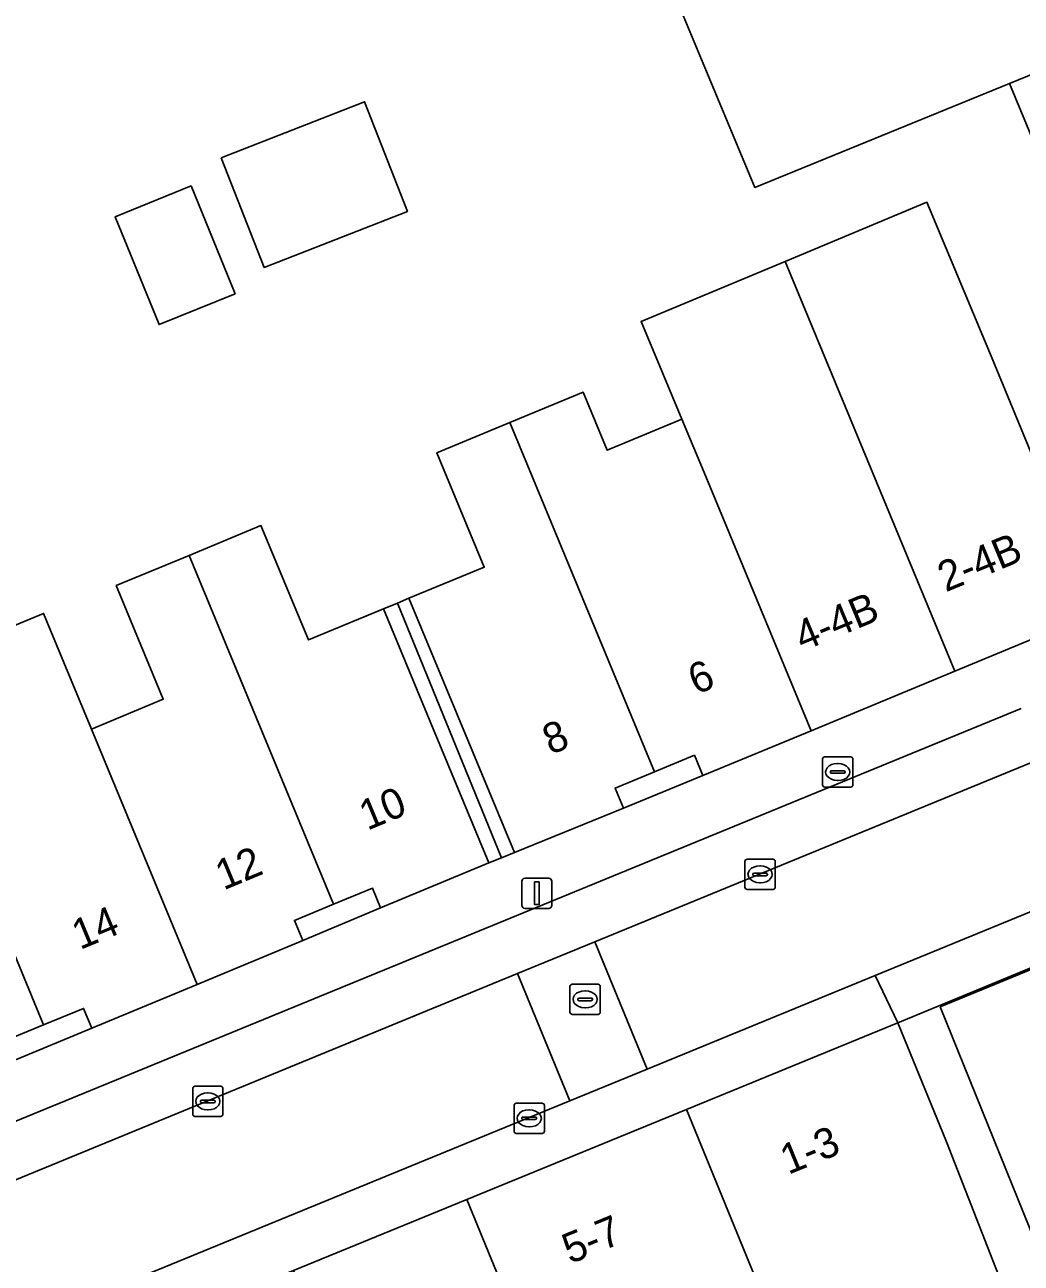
# Model space of a CAD drawing. Extents: x 159371 to 159986, y 382987 to 383597.
# Drawn here: x 159877.92 to 159910.85, y 383362.53 to 383403.47 of the extents above; entities that cross this region are included whole.
import ezdxf

# ---------------------------------------------------------------- set-up
doc = ezdxf.new("R2010")
doc.units = 0
for name, color, linetype in [('IMGEO_Brandkraan', 7, 'Continuous'), ('IMGEO_Erf', 7, 'Continuous'), ('IMGEO_Kolk', 7, 'Continuous'), ('IMGEO_Lichtmast', 7, 'Continuous'), ('IMGEO_Pand', 7, 'Continuous'), ('IMGEO_Pand_nummerreeks', 7, 'Continuous'), ('IMGEO_Pand_overbouw', 7, 'Continuous'), ('IMGEO_Pand_vergunning_verleend', 7, 'Continuous'), ('IMGEO_Parkeervlak_open', 7, 'Continuous'), ('IMGEO_Rijbaan_lokaal_open', 7, 'Continuous'), ('IMGEO_Rioolput', 7, 'Continuous'), ('IMGEO_Voetpad_open', 7, 'Continuous')]:
    doc.layers.add(name, color=color, linetype=linetype)

msp = doc.modelspace()

# ---------------------------------------------------------------- linework, layer by layer
at = {"layer": 'IMGEO_Brandkraan'}
for p, q in [((159904.359, 383379.27), (159905.211, 383379.27)), ((159904.284, 383378.344), (159904.284, 383379.196)), ((159904.772, 383379.05), (159904.797, 383379.05)), ((159905.285, 383379.196), (159905.285, 383378.344)), ((159904.543, 383378.764), (159904.543, 383378.776)), ((159904.981, 383378.727), (159904.583, 383378.727)), ((159904.586, 383378.813), (159904.984, 383378.813)), ((159904.795, 383378.49), (159904.77, 383378.49)), ((159905.027, 383378.776), (159905.027, 383378.764)), ((159905.211, 383378.27), (159904.359, 383378.27))]:
    msp.add_line(p, q, dxfattribs=at)
for points in [[(159904.359, 383379.27), (159905.211, 383379.27)], [(159904.284, 383378.344), (159904.284, 383379.196)], [(159905.285, 383379.196), (159905.285, 383378.344)], [(159905.211, 383378.27), (159904.359, 383378.27)]]:
    msp.add_lwpolyline(points, dxfattribs=at)
for centre, radius, start, end in [((159904.361, 383379.194), 0.0765, 91.552, 178.448), ((159904.361, 383379.194), 0.0765, 91.552, 178.448), ((159905.209, 383379.194), 0.0765, 1.552, 88.448), ((159905.209, 383379.194), 0.0765, 1.552, 88.448), ((159904.583, 383378.773), 0.0403, 85.8775, 175.7526), ((159904.58, 383378.763), 0.0366, 178.938, 274.7102), ((159904.984, 383378.77), 0.043, 264.8664, 352.4533), ((159904.988, 383378.775), 0.0386, 1.7309, 96.639), ((159904.361, 383378.346), 0.0765, 181.552, 268.448), ((159904.361, 383378.346), 0.0765, 181.552, 268.448), ((159905.209, 383378.346), 0.0765, 271.552, 358.448), ((159905.209, 383378.346), 0.0765, 271.552, 358.448)]:
    msp.add_arc(centre, radius, start, end, dxfattribs=at)
for centre, major_axis, ratio, start_param, end_param in [((159904.771, 383378.77), (-0.387, 0.002), 0.722429, 4.712389, 7.853982), ((159904.796, 383378.77), (-0.39, 0.002), 0.717154, 1.570796, 4.712389)]:
    msp.add_ellipse(centre, major_axis=major_axis, ratio=ratio, start_param=start_param, end_param=end_param, dxfattribs=at)
at = {"layer": 'IMGEO_Erf'}
for points in [[(159914.018, 383392.946), (159910.463, 383401.527), (159902.048, 383398.093), (159898.736, 383406.04)], [(159876.16, 383383.024), (159878.542, 383384.012), (159880.125, 383380.191), (159882.499, 383381.175), (159880.942, 383384.933), (159883.351, 383385.931), (159885.727, 383386.916), (159887.294, 383383.134), (159889.776, 383384.162), (159891.341, 383380.385), (159893.256, 383375.765), (159893.678, 383375.937), (159894.099, 383376.108), (159892.185, 383380.728), (159890.617, 383384.511), (159893.102, 383385.541), (159891.536, 383389.318), (159893.955, 383390.32), (159896.375, 383391.323), (159897.169, 383389.407), (159899.635, 383390.428), (159898.286, 383393.665), (159903.049, 383395.65), (159907.734, 383397.602), (159909.884, 383392.444), (159911.446, 383388.674)], [(159938.072, 383368.867), (159934.754, 383367.475), (159932.558, 383372.707), (159933.96, 383373.295), (159932.124, 383377.671), (159934.042, 383378.476), (159932.918, 383381.155), (159927.224, 383378.895), (159915.917, 383374.262), (159914.973, 383373.871), (159906.767, 383370.475), (159908.377, 383366.545), (159911.987, 383357.288)]]:
    msp.add_lwpolyline(points, dxfattribs=at)
for points in [[(159884.413, 383399.072), (159889.145, 383400.924), (159890.563, 383397.303), (159885.831, 383395.451)], [(159883.421, 383398.145), (159884.87, 383394.577), (159882.362, 383393.558), (159880.913, 383397.126)]]:
    msp.add_lwpolyline(points, close=True, dxfattribs=at)
at = {"layer": 'IMGEO_Kolk'}
for p, q in [((159901.719, 383374.96), (159901.719, 383375.812)), ((159901.794, 383375.886), (159902.646, 383375.886)), ((159902.207, 383375.666), (159902.232, 383375.666)), ((159902.72, 383375.812), (159902.72, 383374.96)), ((159901.978, 383375.38), (159901.978, 383375.392)), ((159902.416, 383375.343), (159902.018, 383375.343)), ((159902.021, 383375.429), (159902.419, 383375.429)), ((159902.462, 383375.392), (159902.462, 383375.38)), ((159902.646, 383374.886), (159901.794, 383374.886)), ((159902.23, 383375.106), (159902.205, 383375.106)), ((159883.47, 383367.456), (159883.47, 383368.308)), ((159883.545, 383368.382), (159884.397, 383368.382)), ((159884.471, 383368.308), (159884.471, 383367.456)), ((159883.729, 383367.876), (159883.729, 383367.888)), ((159884.167, 383367.839), (159883.769, 383367.839)), ((159883.772, 383367.925), (159884.17, 383367.925)), ((159883.958, 383368.162), (159883.983, 383368.162)), ((159884.213, 383367.888), (159884.213, 383367.876)), ((159894.164, 383367.822), (159895.016, 383367.822)), ((159884.397, 383367.382), (159883.545, 383367.382)), ((159883.981, 383367.602), (159883.956, 383367.602)), ((159894.089, 383366.896), (159894.089, 383367.748)), ((159894.391, 383367.365), (159894.789, 383367.365)), ((159894.577, 383367.602), (159894.602, 383367.602)), ((159895.09, 383367.748), (159895.09, 383366.896)), ((159894.348, 383367.316), (159894.348, 383367.328)), ((159894.786, 383367.279), (159894.388, 383367.279)), ((159894.6, 383367.042), (159894.575, 383367.042)), ((159894.832, 383367.328), (159894.832, 383367.316)), ((159895.016, 383366.822), (159894.164, 383366.822))]:
    msp.add_line(p, q, dxfattribs=at)
for points in [[(159901.719, 383374.96), (159901.719, 383375.812)], [(159901.794, 383375.886), (159902.646, 383375.886)], [(159902.72, 383375.812), (159902.72, 383374.96)], [(159902.646, 383374.886), (159901.794, 383374.886)], [(159883.47, 383367.456), (159883.47, 383368.308)], [(159883.545, 383368.382), (159884.397, 383368.382)], [(159884.471, 383368.308), (159884.471, 383367.456)], [(159894.164, 383367.822), (159895.016, 383367.822)], [(159884.397, 383367.382), (159883.545, 383367.382)], [(159894.089, 383366.896), (159894.089, 383367.748)], [(159895.09, 383367.748), (159895.09, 383366.896)], [(159895.016, 383366.822), (159894.164, 383366.822)]]:
    msp.add_lwpolyline(points, dxfattribs=at)
for centre, radius, start, end in [((159901.796, 383375.81), 0.0765, 91.552, 178.448), ((159901.796, 383375.81), 0.0765, 91.552, 178.448), ((159902.644, 383375.81), 0.0765, 1.552, 88.448), ((159902.644, 383375.81), 0.0765, 1.552, 88.448), ((159902.018, 383375.389), 0.0403, 85.8775, 175.7526), ((159902.015, 383375.379), 0.0366, 178.938, 274.7102), ((159902.419, 383375.386), 0.043, 264.8664, 352.4533), ((159902.423, 383375.391), 0.0386, 1.7309, 96.639), ((159901.796, 383374.962), 0.0765, 181.552, 268.448), ((159901.796, 383374.962), 0.0765, 181.552, 268.448), ((159902.644, 383374.962), 0.0765, 271.552, 358.448), ((159902.644, 383374.962), 0.0765, 271.552, 358.448), ((159883.547, 383368.306), 0.0765, 91.552, 178.448), ((159883.547, 383368.306), 0.0765, 91.552, 178.448), ((159884.395, 383368.306), 0.0765, 1.552, 88.448), ((159884.395, 383368.306), 0.0765, 1.552, 88.448), ((159883.769, 383367.885), 0.0403, 85.8775, 175.7526), ((159883.766, 383367.875), 0.0366, 178.938, 274.7102), ((159884.17, 383367.882), 0.043, 264.8664, 352.4533), ((159884.174, 383367.887), 0.0386, 1.7309, 96.639), ((159894.166, 383367.746), 0.0765, 91.552, 178.448), ((159894.166, 383367.746), 0.0765, 91.552, 178.448), ((159895.014, 383367.746), 0.0765, 1.552, 88.448), ((159895.014, 383367.746), 0.0765, 1.552, 88.448), ((159883.547, 383367.458), 0.0765, 181.552, 268.448), ((159883.547, 383367.458), 0.0765, 181.552, 268.448), ((159884.395, 383367.458), 0.0765, 271.552, 358.448), ((159884.395, 383367.458), 0.0765, 271.552, 358.448), ((159894.388, 383367.325), 0.0403, 85.8775, 175.7526), ((159894.793, 383367.327), 0.0386, 1.7309, 96.639), ((159894.385, 383367.315), 0.0366, 178.938, 274.7102), ((159894.789, 383367.322), 0.043, 264.8664, 352.4533), ((159894.166, 383366.898), 0.0765, 181.552, 268.448), ((159894.166, 383366.898), 0.0765, 181.552, 268.448), ((159895.014, 383366.898), 0.0765, 271.552, 358.448), ((159895.014, 383366.898), 0.0765, 271.552, 358.448)]:
    msp.add_arc(centre, radius, start, end, dxfattribs=at)
for centre, major_axis, ratio, start_param, end_param in [((159902.206, 383375.386), (-0.387, 0.002), 0.722429, 4.712389, 7.853982), ((159902.231, 383375.386), (-0.39, 0.002), 0.717154, 1.570796, 4.712389), ((159883.957, 383367.882), (-0.387, 0.002), 0.722429, 4.712389, 7.853982), ((159883.982, 383367.882), (-0.39, 0.002), 0.717154, 1.570796, 4.712389), ((159894.576, 383367.322), (-0.387, 0.002), 0.722429, 4.712389, 7.853982), ((159894.601, 383367.322), (-0.39, 0.002), 0.717154, 1.570796, 4.712389)]:
    msp.add_ellipse(centre, major_axis=major_axis, ratio=ratio, start_param=start_param, end_param=end_param, dxfattribs=at)
at = {"layer": 'IMGEO_Lichtmast'}
for p, q in [((159894.345, 383374.36), (159894.345, 383375.16)), ((159894.345, 383375.16), (159894.345, 383374.36)), ((159894.445, 383375.26), (159895.235, 383375.26)), ((159895.235, 383375.26), (159894.445, 383375.26)), ((159895.335, 383375.16), (159895.335, 383374.36)), ((159895.335, 383374.36), (159895.335, 383375.16)), ((159895.235, 383374.26), (159894.445, 383374.26)), ((159894.445, 383374.26), (159895.235, 383374.26))]:
    msp.add_line(p, q, dxfattribs=at)
msp.add_lwpolyline([(159894.765, 383375.135), (159894.915, 383375.135), (159894.915, 383374.385), (159894.765, 383374.385), (159894.765, 383375.135)], dxfattribs=at)
for centre, start, end in [((159894.445, 383375.16), 90, 180), ((159894.445, 383375.16), 90, 180), ((159895.235, 383375.16), 0, 90), ((159895.235, 383375.16), 360, 90), ((159894.445, 383374.36), 180, 270), ((159894.445, 383374.36), 180, 270), ((159895.235, 383374.36), 270, 0), ((159895.235, 383374.36), 270, 0)]:
    msp.add_arc(centre, 0.1, start, end, dxfattribs=at)
at = {"layer": 'IMGEO_Pand'}
for points in [[(159929.666, 383409.619), (159926.604, 383416.76), (159923.474, 383415.417), (159923.137, 383416.203), (159914.242, 383412.388), (159898.736, 383406.04), (159902.048, 383398.093), (159910.463, 383401.527), (159916.891, 383404.15)], [(159929.666, 383409.619), (159916.891, 383404.15), (159910.463, 383401.527), (159914.018, 383392.946), (159916.615, 383394.023), (159917.049, 383394.203), (159916.207, 383396.235), (159915.325, 383398.371), (159915.519, 383398.455), (159915.982, 383398.653), (159924.094, 383402.131), (159925.483, 383398.882), (159928.324, 383400.063), (159932.941, 383401.982)], [(159884.413, 383399.072), (159885.831, 383395.451), (159890.563, 383397.303), (159889.145, 383400.924)], [(159883.421, 383398.145), (159880.913, 383397.126), (159882.362, 383393.558), (159884.87, 383394.577)], [(159903.049, 383395.65), (159908.654, 383382.104), (159913.361, 383384.054), (159911.446, 383388.674), (159909.884, 383392.444), (159907.734, 383397.602)], [(159903.049, 383395.65), (159898.286, 383393.665), (159899.635, 383390.428), (159900.423, 383388.538), (159903.907, 383380.136), (159908.654, 383382.104)], [(159900.423, 383388.538), (159899.635, 383390.428), (159897.169, 383389.407), (159896.375, 383391.323), (159893.955, 383390.32), (159898.735, 383378.778), (159900.047, 383379.322), (159900.325, 383378.652), (159903.907, 383380.136)], [(159893.955, 383390.32), (159891.536, 383389.318), (159893.102, 383385.541), (159890.617, 383384.511), (159892.185, 383380.728), (159894.099, 383376.108), (159897.701, 383377.573), (159897.427, 383378.236), (159898.735, 383378.778)], [(159883.351, 383385.931), (159888.122, 383374.397), (159889.411, 383374.931), (159889.68, 383374.283), (159893.256, 383375.765), (159891.341, 383380.385), (159889.776, 383384.162), (159887.294, 383383.134), (159885.727, 383386.916)], [(159883.622, 383371.749), (159887.111, 383373.195), (159886.834, 383373.863), (159888.122, 383374.397), (159883.351, 383385.931), (159880.942, 383384.933), (159882.499, 383381.175), (159880.125, 383380.191)], [(159880.125, 383380.191), (159878.542, 383384.012), (159876.16, 383383.024), (159873.758, 383382.028), (159873.844, 383381.791), (159878.538, 383370.408), (159879.863, 383370.957), (159880.134, 383370.303), (159883.622, 383371.749)], [(159874.188, 383367.836), (159877.483, 383369.202), (159877.211, 383369.858), (159878.538, 383370.408), (159873.844, 383381.791), (159873.758, 383382.028), (159871.349, 383381.03), (159872.924, 383377.231), (159870.687, 383376.303)], [(159908.377, 383366.545), (159906.767, 383370.475), (159899.783, 383367.614), (159902.941, 383359.909), (159906.149, 383361.223), (159908.195, 383356.229), (159912.029, 383347.048), (159918.322, 383346.711), (159917.563, 383348.528), (159916.399, 383349.622), (159916.315, 383349.823), (159913.983, 383355.409), (159911.987, 383357.288)], [(159902.941, 383359.909), (159899.783, 383367.614), (159892.526, 383364.641), (159897.864, 383351.637), (159899.471, 383347.721), (159901.277, 383347.624), (159903.519, 383347.504), (159901.256, 383353.027), (159899.084, 383358.329)], [(159892.526, 383364.641), (159886.8, 383362.295), (159889.969, 383354.561), (159890.356, 383354.719), (159891.587, 383351.714), (159894.262, 383352.81), (159895.192, 383350.542), (159897.864, 383351.637)]]:
    msp.add_lwpolyline(points, close=True, dxfattribs=at)
at = {"layer": 'IMGEO_Pand_overbouw'}
for points in [[(159889.776, 383384.162), (159891.341, 383380.385), (159893.256, 383375.765), (159893.678, 383375.937), (159890.242, 383384.355)], [(159894.099, 383376.108), (159892.185, 383380.728), (159890.617, 383384.511), (159890.242, 383384.355), (159893.678, 383375.937)]]:
    msp.add_lwpolyline(points, close=True, dxfattribs=at)
at = {"layer": 'IMGEO_Pand_vergunning_verleend'}
msp.add_lwpolyline([(159908.175, 383371.012), (159913.794, 383373.318), (159916.985, 383365.545), (159911.323, 383363.221)], close=True, dxfattribs=at)
at = {"layer": 'IMGEO_Parkeervlak_open'}
for points in [[(159910.848, 383380.871), (159876.516, 383366.772)], [(159874.665, 383364.08), (159894.206, 383372.109), (159896.76, 383373.158), (159914.033, 383380.255)]]:
    msp.add_lwpolyline(points, dxfattribs=at)
at = {"layer": 'IMGEO_Rijbaan_lokaal_open'}
for points in [[(159896.76, 383373.158), (159898.484, 383368.948), (159906.023, 383372.039), (159914.314, 383375.45), (159915.632, 383376.002), (159929.511, 383381.743), (159934.668, 383383.919), (159934.949, 383384.031), (159933.283, 383388.264), (159932.746, 383388.057), (159927.798, 383385.983), (159917.544, 383381.715), (159914.033, 383380.255)], [(159894.206, 383372.109), (159895.93, 383367.9), (159898.484, 383368.948), (159896.76, 383373.158)]]:
    msp.add_lwpolyline(points, close=True, dxfattribs=at)
msp.add_lwpolyline([(159855.412, 383349.492), (159862.546, 383354.138), (159873.236, 383358.594), (159895.93, 383367.9), (159894.206, 383372.109), (159874.665, 383364.08), (159870.989, 383362.556), (159852.647, 383355.016), (159854.94, 383349.623), (159855.086, 383349.291)], dxfattribs=at)
at = {"layer": 'IMGEO_Rioolput'}
for p, q in [((159895.937, 383370.828), (159895.937, 383371.68)), ((159896.012, 383371.754), (159896.864, 383371.754)), ((159896.425, 383371.534), (159896.45, 383371.534)), ((159896.938, 383371.68), (159896.938, 383370.828)), ((159896.196, 383371.248), (159896.196, 383371.26)), ((159896.634, 383371.211), (159896.236, 383371.211)), ((159896.239, 383371.297), (159896.637, 383371.297)), ((159896.68, 383371.26), (159896.68, 383371.248)), ((159896.864, 383370.754), (159896.012, 383370.754)), ((159896.448, 383370.974), (159896.423, 383370.974))]:
    msp.add_line(p, q, dxfattribs=at)
for points in [[(159895.937, 383370.828), (159895.937, 383371.68)], [(159896.012, 383371.754), (159896.864, 383371.754)], [(159896.938, 383371.68), (159896.938, 383370.828)], [(159896.864, 383370.754), (159896.012, 383370.754)]]:
    msp.add_lwpolyline(points, dxfattribs=at)
for centre, radius, start, end in [((159896.014, 383371.678), 0.0765, 91.552, 178.448), ((159896.014, 383371.678), 0.0765, 91.552, 178.448), ((159896.862, 383371.678), 0.0765, 1.552, 88.448), ((159896.862, 383371.678), 0.0765, 1.552, 88.448), ((159896.236, 383371.257), 0.0403, 85.8775, 175.7526), ((159896.233, 383371.247), 0.0366, 178.938, 274.7102), ((159896.637, 383371.254), 0.043, 264.8664, 352.4533), ((159896.641, 383371.259), 0.0386, 1.7309, 96.639), ((159896.014, 383370.83), 0.0765, 181.552, 268.448), ((159896.014, 383370.83), 0.0765, 181.552, 268.448), ((159896.862, 383370.83), 0.0765, 271.552, 358.448), ((159896.862, 383370.83), 0.0765, 271.552, 358.448)]:
    msp.add_arc(centre, radius, start, end, dxfattribs=at)
for centre, major_axis, ratio, start_param, end_param in [((159896.424, 383371.254), (-0.387, 0.002), 0.722429, 4.712389, 7.853982), ((159896.449, 383371.254), (-0.39, 0.002), 0.717154, 1.570796, 4.712389)]:
    msp.add_ellipse(centre, major_axis=major_axis, ratio=ratio, start_param=start_param, end_param=end_param, dxfattribs=at)
at = {"layer": 'IMGEO_Voetpad_open'}
for points in [[(159937.593, 383391.172), (159936.488, 383393.558), (159935.731, 383393.244), (159925.799, 383389.128), (159915.491, 383384.923), (159913.361, 383384.054), (159908.654, 383382.104), (159903.907, 383380.136), (159900.325, 383378.652), (159897.701, 383377.573), (159894.099, 383376.108), (159893.678, 383375.937), (159893.256, 383375.765), (159889.68, 383374.283), (159887.111, 383373.195), (159883.622, 383371.749), (159880.134, 383370.303), (159877.483, 383369.202)], [(159876.516, 383366.772), (159910.848, 383380.871)], [(159869.905, 383339.262), (159881.768, 383337.219), (159881.859, 383337.661), (159881.331, 383337.761), (159869.846, 383339.731), (159869.208, 383341.301), (159865.29, 383351.045), (159866.522, 383353.987), (159874.945, 383357.438), (159880.193, 383359.588), (159886.8, 383362.295), (159892.526, 383364.641), (159899.783, 383367.614), (159906.767, 383370.475), (159906.023, 383372.039), (159898.484, 383368.948), (159895.93, 383367.9), (159873.236, 383358.594), (159862.546, 383354.138), (159855.412, 383349.492)]]:
    msp.add_lwpolyline(points, dxfattribs=at)
for points in [[(159900.325, 383378.652), (159900.047, 383379.322), (159898.735, 383378.778), (159897.427, 383378.236), (159897.701, 383377.573)], [(159914.314, 383375.45), (159906.023, 383372.039), (159906.767, 383370.475), (159914.973, 383373.871)], [(159889.68, 383374.283), (159889.411, 383374.931), (159888.122, 383374.397), (159886.834, 383373.863), (159887.111, 383373.195)], [(159880.134, 383370.303), (159879.863, 383370.957), (159878.538, 383370.408), (159877.211, 383369.858), (159877.483, 383369.202)]]:
    msp.add_lwpolyline(points, close=True, dxfattribs=at)

# ---------------------------------------------------------------- texts
at = {"layer": 'IMGEO_Pand_nummerreeks'}
for s, rotation, p in [('2-4B', 22.5031, (159908.351, 383384.706)), ('4-4B', 22.5172, (159903.623, 383382.746)), ('6', 22.4198, (159900.107, 383381.313)), ('8', 22.4172, (159895.296, 383379.328)), ('10', 22.5624, (159889.24, 383376.825)), ('12', 22.5624, (159884.488, 383374.851)), ('14', 22.5631, (159879.745, 383372.881)), ('1-3', 22.2766, (159903.148, 383365.448)), ('5-7', 22.2776, (159895.942, 383362.496))]:
    msp.add_text(s, height=1, rotation=rotation, dxfattribs=at).set_placement(p)

doc.saveas('drawing.dxf')
